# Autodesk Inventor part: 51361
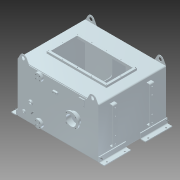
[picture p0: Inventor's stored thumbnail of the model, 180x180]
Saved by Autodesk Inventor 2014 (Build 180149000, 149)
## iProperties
Shininess: 20.0
Length Units: 11272
Angle Units: 11279
Time Units: 11290
Mass Units: 11286
Length Display Precision: 3
Angle Display Precision: 2
Company: Autodesk, Inc.
Created: 2002-07
Part Number: 51361
Project: 2039
Material: Stainless Steel 316
Description: TANK WLDMT
Document SubType Name: Modeling
Designer: Autodesk, Inc.
Density: 8.182 g/cm^3
Mass: 207336 g
Surface Area: 74176.4 cm^2
Volume: 25340.5 cm^3
Appearance: Stainless Steel
Density: 0.0
Volumn: 0.0
Area: 0.0
PropertySet Name: Model Information
Control State: 0
Master: False
Checked Out: True
Last Check In By: JT
Last Check In Date: 2003-06-20
Title: TANK WLDMT
Author: Autodesk, Inc.
Revision Number: A
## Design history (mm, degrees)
derived "51361.iam"
  feature "41461.ipt:1"
  feature "47278.ipt:1"
  feature "47279.ipt:1"
  feature "49485.ipt:1"
  feature "41462.ipt:1"
  feature "245093.ipt:1"
  feature "51433.ipt:1"
  feature "51436.ipt:3"
  feature "51436.ipt:4"
  feature "241969.ipt:1"
  feature "241969.ipt:3"
  feature "50730.ipt:1"
  feature "241969.ipt:4"
  feature "48182.ipt:1"
  feature "48182.ipt:2"
  feature "51435.ipt:1"
  feature "51560.ipt:1"
  feature "51697.ipt:1"
  feature "243109.ipt:1"
  feature "240811.ipt:1"
  feature "240811.ipt:2"
  feature "240811.ipt:3"
  feature "240811.ipt:4"
  feature "240811.ipt:5"
  feature "240811.ipt:6"
  feature "51432.ipt:1"
  feature "51431.ipt:1"
  feature "51436.ipt:1"
  feature "51436.ipt:2"
  feature "51437.ipt:1"
  feature "51437.ipt:2"
sketch "Sketch3"
  geometry: C1 r 5.296 at (-89.7, 26.187) reference; C2 r 5.296 at (-11.9, 69.063) reference; C3 r 5.296 at (-11.9, 26.187) reference; C4 r 5.296 at (-89.7, 69.063) reference
extrude "Extrusion2" join sketch "Sketch3" distance "d17" = 25.4; taper "d18" = 0 deg
body "Solid1"
